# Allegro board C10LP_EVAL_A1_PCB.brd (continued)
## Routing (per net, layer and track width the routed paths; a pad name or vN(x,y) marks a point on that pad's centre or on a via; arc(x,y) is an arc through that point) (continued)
C10_M10_IO0: length 44.6
  TOP w0.135: U3.K8 v2(46.15,67.88) ; v2(39.84,33.68) U1.E8
  ART03 w0.102: v2(46.15,67.88) 45.75,68.27 45.75,68.81 45.5,69.06 43.68,69.06 42.52,67.89 42.52,65.13 42.9,64.74 42.9,63.5 43.56,62.84 43.56,60.68 45.8,58.45 45.8,50.27 39.62,44.09 39.62,36.61 40.26,35.97 40.26,34.1 40.13,33.97 v2(39.84,33.68)
C10_M10_IO1: length 50.4
  TOP w0.135: v2(39.04,33.68) U1.E7 ; U3.J8 v2(46.15,67.07)
  ART03 w0.102: v2(39.04,33.68) 38.63,34.09 38.63,35.69 38.13,36.2 38.13,45.52 39.22,46.61 40.03,46.61 44.55,51.13 44.55,56.36 43.64,57.28 43.64,58.52 42.77,59.39 42.09,59.39 41.76,59.72 41.76,61.49 40.49,62.76 40.49,64.41 40.74,64.67 40.74,68.33 41.63,69.22 42.95,69.22 43.31,69.57 46.15,69.57 46.69,69.04 46.69,67.62 v2(46.15,67.07)
C10_M10_IO2: length 41.8
  TOP w0.135: U3.L10 v2(44.55,67.87) ; v2(39.84,32.88) U1.F8
  ART03 w0.102: v2(44.55,67.87) 44.3,68.12 43.66,68.12 43.33,67.79 43.33,63.63 43.97,62.99 43.97,60.88 46.2,58.65 46.2,49.99 40.69,44.48 40.69,38.51 39.85,37.67 39.85,36.7 40.49,36.07 40.49,33.53 40.23,33.27 v2(39.84,32.88)
C10_M10_IO3: length 58.3
  TOP w0.135: U3.L5 v2(49.35,68.67) ; v2(35.84,35.28) U1.C3
  ART03 w0.102: v2(35.84,35.28) 35.38,35.28 35.37,35.29 34.96,35.29 33.07,37.19 33.07,46.48 35.53,48.95 41,48.95 42.8,50.75 42.8,57.66 42.6,57.86 41.45,57.86 40.97,58.34 40.97,61.11 39.67,62.41 39.67,64.82 39.14,65.35 39.14,68.22 41.91,70.99 48.41,70.99 49.35,70.06 v2(49.35,68.67)
C10_MSEL0: length 8.7
  TOP w0.135: v2(44.64,31.28) U1.H13
  BOTTOM w0.135: R23.1 R22.1 49,31.32 47.52,32.79 46.39,32.79 45.84,32.24 45.84,31.92 45.6,31.68 45.04,31.68 v2(44.64,31.28)
C10_MSEL1: length 9.7
  TOP w0.135: v2(43.84,31.28) U1.H12
  BOTTOM w0.135: R20.1 R19.1 50.13,32.16 48.62,32.16 47.65,33.12 46.25,33.12 45.61,32.48 45.6,32.48 44.48,32.48 44.24,32.24 44.24,31.68 v2(43.84,31.28)
C10_MSEL2: length 7
  TOP w0.135: U1.G12 v2(43.84,32.08)
  BOTTOM w0.135: R17.1 R18.1 48.12,33.53 45.97,33.53 45.72,33.27 45.61,33.27 45.6,33.28 44.48,33.28 44.24,33.04 44.24,32.72 43.84,32.32 v2(43.84,32.08)
C10_NCE: length 7.5
  TOP w0.135: v2(35.84,29.68) U1.J3
  ART03 w0.102: v2(35.84,29.68) 35.55,29.97 30.66,29.97 v1(30.05,29.36)
  BOTTOM w0.135: R8.2 v1(30.05,29.36)
C10_NCONFIG: length 63
  TOP w0.135: v1(66.84,45.83) 66.84,46.67 67.02,46.85 C205.1 68.38,46.85 68.4,46.84 S1.2 ; v2(37.44,31.28) U1.H5
  ART03 w0.102: v1(48.29,40.26) 48.29,39.62 53.92,33.99 62.36,33.99 67.34,38.96 67.34,45.34 v1(66.84,45.83) ; v2(37.44,31.28) 37.03,31.69 37.03,40.87 v1(35.66,42.24)
  BOTTOM w0.135: v2(37.44,31.28) 37.04,31.68 36.48,31.68 36.1,31.68 36.02,31.6 R2.2 ; v1(48.29,40.26) 41.1,40.26 39.12,42.24 v1(35.66,42.24)
C10_NSTATUS: length 92.3
  TOP w0.135: v2(36.64,32.88) U1.F4 ; v2(53.14,70.08) 52.55,69.49 51.77,69.49 U3.M2
  ART03 w0.102: v2(36.64,32.88) 36.25,33.27 33.06,33.27 24.12,42.21 21.18,42.21 20.19,43.21 20.19,44.75 19.68,45.26 19.68,46.48 19.05,47.12 19.05,49.78 20.42,51.16 20.42,55.3 21.03,55.91 28.52,55.91 30.02,54.41 31.7,54.41 32.44,53.67 37.39,53.67 37.8,54.08 37.8,56.01 38.13,56.34 39.37,56.34 40.56,57.53 40.56,60.93 39.19,62.31 39.19,63.17 38.63,63.73 38.63,68.33 41.71,71.4 52.32,71.4 53.14,70.59 v2(53.14,70.08)
  BOTTOM w0.135: v2(36.64,32.88) 36.24,33.28 33.43,33.28 R1.2
C10_RESETN: length 38
  TOP w0.135: U1.J15 46.24,30.48 47.9,30.48 48.26,30.12 50.67,30.12 51.08,29.72 R136.2 51.45,29.35 51.87,28.93 56.46,28.93 v1(58.8,26.59) ; v1(66.84,42.53) C204.1 68.29,42.53 68.4,42.42 S2.2
  BOTTOM w0.135: v1(58.8,26.59) 60.02,27.81 60.02,32.23 65.13,37.34 65.81,37.34 67.36,38.89 67.36,42.01 v1(66.84,42.53)
C10_RG_TXCLK: length 3.6
  TOP w0.135: U1.D3 v2(35.84,34.48)
  BOTTOM w0.135: v2(35.84,34.48) 33.76,34.48 R305.2
C10_RG_TXCTL: length 2.8
  TOP w0.135: v2(38.24,34.48) U1.D6
  BOTTOM w0.135: v2(38.24,34.48) 38.64,34.88 38.64,36 R301.2
C10_RG_TXD0: length 3.7
  TOP w0.135: v2(38.24,33.68) U1.E6
  BOTTOM w0.135: v2(38.24,33.68) 37.84,34.08 37.84,35.73 R306.2
C10_RG_TXD1: length 1.5
  TOP w0.135: v2(35.84,36.88) U1.A3
  BOTTOM w0.135: R303.2 36.14,37.18 v2(35.84,36.88)
C10_RG_TXD2: length 2.5
  TOP w0.135: v2(35.84,36.08) U1.B3
  BOTTOM w0.135: v2(35.84,36.08) 35.44,36.48 35.44,37.42 R304.2
C10_RG_TXD3: length 1.9
  TOP w0.135: v2(35.04,36.88) U1.A2
  BOTTOM w0.135: v2(35.04,36.88) 34.91,36.88 R302.2
C10_USB_CLK: length 3.1
  TOP w0.135: v2(41.43,37.85) 41.48,37.8 41.48,36.12 U1.B9
  BOTTOM w0.135: R248.2 41.41,37.86 v2(41.43,37.85)
C10_VCCA: length 6.1
  TOP w0.254: R67.2 v1(52.44,40.32)
  BOTTOM w0.305: L17.1 51.03,36.37 R64.1 51.54,40.32 v1(52.44,40.32)
C10_VCCA_FLT: length 17.1
  TOP w0.305: U1.L12 v2(43.84,28.08) ; U1.F5 v2(37.44,32.88) ; U1.L5 v2(37.44,28.08) ; U1.F12 v2(43.84,32.88)
  ART03 w0.305: v2(43.84,28.08) 43.83,28.08 43.38,27.64
  ART03 w0.406: v2(43.04,33.68) 43.05,33.68 43.84,32.89 v2(43.84,32.88) 43.45,32.49 43.41,32.49
  BOTTOM w0.135: v2(37.44,28.08) 37.04,28.48 37.04,29.84 37.03,29.85 37.03,29.96
  BOTTOM w0.254: 37.03,29.96 R7.1
  BOTTOM w0.305: L17.2 R17.2 50.13,34.25 50.77,34.9 51.28,34.9 52.02,34.16 52.02,32.69 51.71,32.38 R19.2 R22.2 ; R4.1 R7.1
C10_VCCD_PLL: length 9.1
  TOP w0.305: U1.N4 37.03,26.88 v2(36.64,26.49) ; v2(44.64,34.48) U1.D13 ; v2(44.64,26.48) U1.N13 ; U1.D4 37.04,34.08 v2(36.64,34.48)
  ART03 w0.305: v1(48.59,22.2) 47.75,23.04 47.75,24.28 47.14,24.89 47.14,25.6 46.27,26.48 v2(44.64,26.48)
  vias: v1(53.39,27.84) v1(53.42,27.15) v1(54.13,27.86) v1(54.18,27.15)
C10_VCCINT: length 48.8
  TOP w0.254: R65.2 v1(59.96,36.13)
  TOP w0.305: v2(41.44,32.08) U1.G9 ; U1.K10 v2(42.24,28.88) ; v2(41.44,28.88) U1.K9 ; C143.2 49.9,26.59 v1(48.18,26.59) ; v2(42.24,32.08) U1.G10 ; v2(43.04,32.88) U1.F11 ; v2(42.24,27.28) U1.M11 ; v2(39.04,28.88) U1.K7 ; v2(38.24,31.28) U1.H6 ; v2(43.04,31.28) U1.H11 ; v2(38.24,32.08) U1.G6 ; v2(39.04,32.88) U1.F7 ; v2(38.24,28.08) U1.L6 ; v2(43.84,29.68) U1.J12 ; v2(43.04,28.88) U1.K11 ; U1.M9 41.01,27.68 v2(40.64,27.3) ; v2(38.24,29.68) U1.J6 ; v2(39.84,32.08) U1.G8 ; v2(39.04,32.08) U1.G7
  BOTTOM w0.254: R63.1 55.26,22.4 53.17,22.4 52.75,22.4 52.04,23.11 52.04,29.69 57.12,34.77 57.12,35.98 57.12,36.42 58.14,37.44 59.08,37.44 59.66,36.86 59.66,36.43 v1(59.96,36.13)
  BOTTOM w0.305: C130.1 48.28,26.69 v1(48.18,26.59) ; C194.1 47.7,21.92 v1(48.56,21.06) ; v1(51.51,27.2) 51.49,27.18 51.46,27.18 50.94,26.66 C142.1 ; C193.1 50.01,23.72 50.42,24.13 v1(50.42,24.61)
  BOTTOM w0.406: v2(43.84,29.68) 44.23,30.07 C136.1 ; v2(38.24,31.28) 38.44,31.08 C139.2 ; C134.1 41.02,28.46 v2(41.44,28.88) ; v2(43.04,31.28) 42.84,31.08 C138.2 ; v2(41.44,32.08) 41.03,31.67 C141.1 ; C129.1 v2(40.64,27.3) ; C124.1 39.84,32.08 v2(39.84,32.08)
  vias: v3(59.77,21.56) v3(59.77,20.83) v3(59.77,20.09) v3(60.5,21.62) v3(60.5,20.85) v3(60.5,20.09) v3(60.48,19.3) v3(61.24,21.62) v3(61.24,20.85) v3(61.24,20.12) v3(61.21,19.33)
C10_VCCIO_1.8V: length 6.4
  TOP w0.305: U1.P10 41.87,26.08 42.16,25.79 42.16,25.76 v2(42.21,25.7) ; v2(44.64,25.68) U1.P13 ; v2(47.04,24.08) U1.T16
  BOTTOM w0.305: 47.07,24.11 v2(47.04,24.08)
  BOTTOM w0.406: 47.07,24.11 47.07,25.92 R12.1 ; C122.2 44.7,25.62 v2(44.64,25.68) ; C197.1 42.24,25.68 v2(42.21,25.7)
C10_VCCIO_3.3V: length 33.9
  TOP w0.254: R78.2 v1(52.49,47.08)
  TOP w0.305: v2(36.64,25.68) U1.P4 ; v2(36.64,35.28) 37.04,34.88 U1.C4 ; v2(45.44,33.68) U1.E14 ; v2(35.84,27.28) U1.M3 ; v2(35.84,32.08) U1.G3 ; U1.T1 34.59,24.48 v2(34.24,24.83) ; v2(42.24,35.28) U1.C10 ; v2(39.04,35.28) U1.C7 ; v2(39.04,25.68) U1.P7 ; v2(44.64,35.28) U1.C13 ; v2(45.44,28.88) U1.K14 ; R136.1 R207.1 49.47,28.46 v1(49.35,28.58) ; v2(47.04,36.88) U1.A16 ; v2(34.24,36.88) U1.A1 ; v2(35.84,28.88) U1.K3 ; v2(35.84,33.68) U1.E3 ; v2(44.64,27.28) U1.M14 ; v2(45.44,32.08) U1.G14
  TOP w0.381: R276.1 29.98,25.49 v1(29.96,25.51) R277.1
  ART03 w0.305: 45.19,31.88 45.39,32.08 v2(45.44,32.08)
  BOTTOM w0.254: v1(40.13,39.88) R278.1 R279.1
  BOTTOM w0.305: v1(52.49,47.08) 52.32,47.24 48.48,47.24 R77.1 ; R1.1 33.4,31.8 33.62,31.59 34.39,31.59 R2.1 34.4,32 34.71,32.31 35.61,32.31 v2(35.84,32.08)
  BOTTOM w0.381: v2(35.84,28.88) 35.19,28.88 R288.1
  BOTTOM w0.406: C195.1 47.78,45.47 47.8,45.49 R77.1 ; v1(49.35,28.58) 49.35,29.17 49.05,29.48 R246.1 R21.1 R16.1 46.04,29.48 v2(45.44,28.88) ; C120.2 34.19,36.83 v2(34.24,36.88) ; C196.1 39.03,25.67 v2(39.04,25.68)
  vias: v1(47.8,43.54) v1(47.83,42.85) v1(47.83,42.16)
ENET_CLK_125M: length 60.9
  TOP w0.135: U1.T8 40.16,24.4 40.16,22.4 39.14,21.39 39.14,20.37 37.85,19.08 37.85,16 39.88,13.97 39.88,12.75 42.09,10.54 57.33,10.54 59.77,12.98 62.05,12.98 62.33,12.7 65.35,12.7 v1(66.45,11.61)
  BOTTOM w0.135: R152.2 71.78,23.49 71.2,24.08 68.1,24.08 67.74,23.72 67.74,21.51 67.11,20.88 67.11,12.27 v1(66.45,11.61)
ENET_INT: length 24.8
  TOP w0.135: U1.B5 37.47,36.05 37.47,37.31 33.93,40.84 25.98,40.84 22.99,43.84 22.99,44.54 R97.1
  TOP w0.142: R97.1 22.4,45.42 23.37,46.38 23.37,47.78 23.91,48.32 U14.47
ENET_LED0: length 24.4
  TOP w0.135: v1(17.78,58.52) 17.12,57.86 D10.1 ; U14.24 31.66,53.32 32.07,53.73 R109.2 C55.2 v1(32.84,57.51)
  ART03 w0.102: v1(32.84,57.51) 32.23,58.12 20.95,58.12 20.55,58.52 v1(17.78,58.52)
ENET_LED1: length 26.1
  TOP w0.135: v1(16.89,58.6) 16.1,59.39 D11.1 ; U14.23 31.92,52.82 32.92,53.82 v1(32.92,56.11)
  ART03 w0.102: v1(32.92,56.11) 32.23,56.79 26.04,56.79 25.43,57.4 18.08,57.4 v1(16.89,58.6)
  BOTTOM w0.135: C56.2 R112.2 16.87,58.62 v1(16.89,58.6)
ENET_LED2: length 28.3
  TOP w0.135: v1(17.86,59.36) 16.33,60.88 D12.1 ; U14.22 32.05,52.32 33.64,53.91 C65.2 R114.2 v1(32.84,59.03)
  ART03 w0.102: v1(17.86,59.36) 18.26,58.95 20.88,58.95 21.26,58.57 32.38,58.57 v1(32.84,59.03)
ENET_MDC: length 32
  TOP w0.135: R297.1 20,45.15 19.56,44.7 19.56,43.43 20.5,42.49 23.04,42.49 25.6,39.93 33.48,39.93 36.65,36.75 36.65,36.07 U1.B4
  TOP w0.142: R297.1 20.68,45.63 21.04,45.63 22.38,46.96 22.38,48.57 22.21,48.74 22.21,50.15 23.38,51.32 U14.41
ENET_MDIO: length 28.2
  TOP w0.135: U1.A4 37.04,37.1 33.76,40.39 25.78,40.39 23.19,42.98 22.17,42.98 21.84,43.31 21.84,44.49 R98.1 21.21,45.14 21.34,45.26
  TOP w0.142: U14.42 23.41,50.82 22.66,50.06 22.66,48.92 22.86,48.72 22.86,46.79 21.34,45.26
ENET_REGO: length 4
  TOP w0.254: 21.84,53.17 22.68,52.32 U14.39
  TOP w0.305: 20.73,53.17 21.84,53.17
ENET_RG_RXCLK: length 17.7
  TOP w0.135: U1.B8 39.84,36.08 39.84,39.31 37.87,41.27 37.87,42.65 36.28,44.23 R102.1
ENET_RG_RXCTL: length 18.2
  TOP w0.135: R103.1 26.4,41.3 34.11,41.3 37.84,37.57 U1.A5
ENET_RG_RXD0: length 17.1
  TOP w0.135: U1.A7 39.44,38.86 37.03,41.27 37.03,42.65 36.4,43.28 28.74,43.28 R104.1
ENET_RG_RXD1: length 18.9
  TOP w0.135: R105.1 26.64,43.46 27.38,42.72 35.97,42.72 36.37,42.32 36.37,41.15 39.04,38.48 39.04,36.08 U1.B7
ENET_RG_RXD2: length 17.5
  TOP w0.135: R106.1 25.63,43.74 27.15,42.21 34.54,42.21 38.64,38.12 U1.A6
ENET_RG_RXD3: length 18.7
  TOP w0.135: R107.1 26.96,41.76 34.32,41.76 38.25,37.82 38.25,36.07 U1.B6
ENET_RG_TXCLK: length 13.6
  TOP w0.142: v1(30.07,44.83) 29.72,45.19 29.72,45.75 29.11,46.36 U14.9
  BOTTOM w0.135: v1(30.07,44.83) 30.07,39.05 31.03,38.1 32.56,38.1 33.1,37.57 R305.1
ENET_RG_TXCTL: length 14.9
  TOP w0.135: U14.15 32.08,48.82 33.07,47.83 33.07,45.39 v1(33.63,44.83)
  BOTTOM w0.135: R301.1 37.24,38.29 37.24,39.65 33.63,43.26 v1(33.63,44.83)
ENET_RG_TXD0: length 14.7
  TOP w0.135: v1(31.8,45.69) 32.26,45.69 32.61,46.05 32.61,47.6 31.89,48.32 U14.14
  BOTTOM w0.135: R306.1 36.73,37.73 36.73,39.4 32.28,43.84 32.28,45.21 v1(31.8,45.69)
ENET_RG_TXD1: length 14.7
  TOP w0.135: v1(31.78,44.86) 31.32,45.31 31.32,46.1 30.61,46.81 U14.12
  BOTTOM w0.135: v1(31.78,44.86) 31.78,42.32 31.91,42.19 32.48,42.19 32.61,42.05 32.61,41.79 32.48,41.65 31.91,41.65 31.78,41.52 31.78,41.22 31.93,41.07 33.28,41.07 33.41,40.94 33.41,40.5 33.55,40.36 33.81,40.36 33.95,40.5 33.95,40.99 34.08,41.12 34.37,41.12 36.14,39.34 R303.1
ENET_RG_TXD2: length 13.6
  TOP w0.135: U14.11 30.11,46.68 30.84,45.95 v1(30.84,45.69)
  BOTTOM w0.135: v1(30.84,45.69) 31.29,45.24 31.29,39.99 31.43,39.85 31.68,39.85 31.82,39.99 31.82,40.4 31.95,40.54 32.22,40.54 32.35,40.4 32.35,39.99 32.49,39.85 34.85,39.85 35.1,39.6 R304.1
ENET_RG_TXD3: length 14.1
  TOP w0.135: U14.10 29.61,46.54 30.25,45.9 30.25,45.42 v1(30.81,44.86)
  BOTTOM w0.135: R302.1 33.49,38.65 33.36,38.78 33.36,39.16 33.17,39.34 32.96,39.34 32.82,39.21 32.82,38.78 32.69,38.65 32.27,38.65 32.14,38.78 32.14,39.21 31.98,39.37 31.73,39.37 31.6,39.24 31.6,38.78 31.46,38.65 31.18,38.65 30.81,39.01 v1(30.81,44.86)
ENET_RSTN: length 18.4
  TOP w0.135: v1(33.6,45.69) 33.62,45.71 R96.1 C54.2 32.84,48.69 32.21,49.32 U14.16 ; v2(38.24,35.28) U1.C6
  ART03 w0.102: v1(33.6,45.69) 37.47,41.83 37.47,36.05 v2(38.24,35.28)
ENET_TCK: length 3.1
  TOP w0.135: v1(32.21,50.85) 31.39,50.85 U14.19
  BOTTOM w0.135: R99.1 31.24,51.82 v1(32.21,50.85)
ENET_TDI: length 2
  TOP w0.135: TP6.1 32.61,50.32 U14.18
ENET_TDO: length 1.3
  TOP w0.135: TP5.1 31.36,51.82 U14.21
ENET_TMS: length 3.5
  TOP w0.135: U14.20 32.01,51.32 32.05,51.36 32.59,51.36 TP7.1
ENET_VDD_1V: length 5.5
  TOP w0.254: v1(32.08,46.63) 32.08,47.37 31.63,47.82 U14.13 ; U14.8 28.61,46.68 28.68,46.61 28.68,46.1 v1(28.88,45.9) ; v1(22.78,51.61) 22.99,51.82 U14.40 ; U14.17 v1(32.27,49.82)
  vias: v1(21.01,49.83) v1(20.95,48.82) v1(21.64,49.45)
ENET_VDD_3.3V: length 24.8
  TOP w0.203: U14.45 23.9,49.32 v1(23.47,48.89)
  TOP w0.254: U14.38 23.81,52.82 23.32,53.31 23.32,53.45 C64.2 ; U14.25 30.61,54.84 v1(30.76,54.99) ; U14.2 v1(25.61,46.23) ; v1(25.45,54.94) 25.61,54.79 U14.35 ; v1(28.09,46.2) 28.11,46.22 U14.7 ; v1(28.12,54.97) 28.11,54.95 U14.30
  TOP w0.305: R97.2 v1(22.4,43.56)
  TOP w0.381: v1(21.54,54.56) 21.79,54.31 v1(22.33,54.31) 22.9,53.73 C64.2 ; R98.2 21.21,43.94 v1(20.83,43.56) 20.19,44.2 R297.2
  TOP w0.406: R96.2 v1(34.51,47.02)
  BOTTOM w0.381: v1(23.47,48.89) 23.6,49.02 C60.2 ; v1(28.09,46.2) 28.11,46.22 28.11,46.76 C62.2 ; R99.2 31.25,53.54 31.8,53.54 31.85,53.49 31.85,52.43 33.58,50.7 33.58,47.94 v1(34.51,47.02) ; v1(25.61,46.23) 26.29,46.91 C61.2
  BOTTOM w0.406: C57.2 25.91,54.98 25.87,54.94 v1(25.45,54.94) ; C58.2 v1(28.12,54.97)
ENET_XTAL1: length 5.3
  TOP w0.135: U14.36 25.11,54.54 C44.1 23.37,56.27
  TOP w0.142: 23.37,56.27 23.37,57.95 23.5,58.08 Y2.3
ENET_XTAL2: length 4.3
  TOP w0.135: C53.1 24.36,54.22 U14.37
  TOP w0.142: Y2.1 22.62,55.96 C53.1
EXT_JTAG_TCK: length 46.9
  TOP w0.135: v1(53.87,83.41) 54.58,82.7 R57.2 54.6,81.41 R58.1 53.21,81.28 52.91,80.98 51.31,80.98 50.44,81.84 J2.1 ; v2(41.78,65.99) 42.07,66.27 42.95,66.27 U3.J12
  ART03 w0.102: v1(38,79.63) 37.24,80.39 37.24,81.89 37.62,82.27 52.73,82.27 v1(53.87,83.41)
  BOTTOM w0.135: v2(41.78,65.99) 41.53,65.74 39.4,65.74 38,67.13 v1(38,79.63)
EXT_JTAG_TDI: length 33.8
  TOP w0.135: J2.9 v1(40.28,80.77) ; U3.J9 v2(45.35,67.07)
  ART03 w0.102: v1(39.98,67.54) 39.98,68.05 41.5,69.57 42.9,69.57 43.41,70.08 46.28,70.08 46.91,69.44 46.91,66.95 46.63,66.67 45.75,66.67 v2(45.35,67.07)
  BOTTOM w0.135: v1(39.98,67.54) 38.61,68.91 38.61,79.98 38.25,80.34 R61.2 37.55,80.77 v1(40.28,80.77)
EXT_JTAG_TDO: length 25.4
  TOP w0.135: J2.3 v1(47.9,80.72) ; v1(39.52,70.76) 40.23,70.05 40.23,68.71 41.87,67.07 42.95,67.07 U3.K12
  ART03 w0.102: v1(47.9,80.72) 47.14,79.96 41.68,79.96 40.01,78.28 40.01,75.06 39.42,74.47 39.42,70.87 v1(39.52,70.76)
EXT_JTAG_TMS: length 36.2
  TOP w0.135: R60.2 53.47,79.6 v1(53.44,79.58) 52.88,80.14 46.08,80.14 45.36,80.85 J2.5 ; v1(40.51,73.28) 40.51,71.25 41,70.76 41,68.91 41.63,68.27 U3.L13
  ART03 w0.102: v1(40.51,73.28) 40.51,77.29 42.72,79.5 53.37,79.5 v1(53.44,79.58)
EXT_VREF: length 11.2
  TOP w0.147: U3.D3 v2(50.16,62.29)
  BOTTOM w0.305: v2(50.16,62.29) 50.16,62.15 51.24,61.07 C213.2
  BOTTOM w0.406: R228.1 48.06,57.4 48.79,56.67 R295.2 51.32,58.48 C212.1 51.24,58.56 C213.2
EXT_VREF_AR: length 60.7
  TOP w0.381: v1(28.4,13.13) 27.01,13.13 R308.2
  ART03 w0.305: v1(42.32,57.33) 40.36,55.37 40.36,51.74 39.29,50.67 34.44,50.67 29.46,45.69 29.46,38.35 v1(30.07,37.74)
  BOTTOM w0.305: v1(42.32,57.33) 44.07,57.33 44.3,57.1 45.21,57.1 45.52,57.4 R228.2 ; v1(30.07,37.74) 30.07,35.92 31.9,34.09 31.9,27.1 30.78,25.98 30.78,20.55 31.24,20.09 31.24,17.45 28.93,15.14 28.93,13.67 v1(28.4,13.13)
FX2_D_N: length 17.4
  TOP w0.132: U6.9 67.4,70.69 67.49,70.61 69.91,70.61 70.25,70.94 71.15,70.94 71.48,70.62 71.68,70.62 U5.2 72.03,70.61 76.1,70.61 77.24,69.47 77.24,66.54 J17.2
FX2_D_P: length 17.3
  TOP w0.132: U6.8 67.4,70.19 67.49,70.28 69.94,70.28 70.29,69.93 71.14,69.93 71.42,70.21 71.73,70.21 U5.1 72.03,70.28 75.96,70.28 76.91,69.33 76.91,66.67 75.31,65.07 J17.3
FX2_FLAGA: length 17.9
  TOP w0.135: U6.29 58.78,73.19 58.5,73.48 58.5,73.58 v1(58.09,73.99) ; U3.M9 46.15,69.48 46.15,71.73 46.63,72.21 v1(46.63,73.63)
  ART03 w0.102: v1(46.63,73.63) 57.73,73.63 v1(58.09,73.99)
FX2_FLAGB: length 15.5
  TOP w0.135: v1(58.12,73) 58.42,72.69 U6.30 ; v1(47.37,73.13) 46.99,72.75 46.99,71.5 46.55,71.06 U3.N8
  ART03 w0.102: v1(58.12,73) 57.99,73.13 v1(47.37,73.13)
FX2_FLAGC: length 17
  TOP w0.135: U6.31 58.06,72.19 55.8,74.45 49.68,74.45 47.37,72.14 47.37,71.04 46.94,70.61 46.94,69.47 U3.M8
FX2_PA0: length 15.6
  TOP w0.135: U6.33 58.32,71.19 58.32,71.19 58.07,71.19 57.74,71.52 57.74,71.85 55.68,73.91 49.78,73.91 47.75,71.88 47.75,70.89 47.35,70.48 U3.N7
FX2_PA1: length 15.8
  TOP w0.135: U6.34 58.17,70.69 58.1,70.76 57.87,70.76 57.3,71.32 57.3,71.4 55.24,73.46 49.96,73.46 48.13,71.63 48.13,70.62 47.75,70.23 47.75,69.47 U3.M7
FX2_PA2: length 14.1
  TOP w0.135: U6.35 57.79,70.19 54.99,73 50.04,73 48.5,71.46 48.5,70.23 U3.N6
FX2_PA3: length 13.2
  TOP w0.135: U3.N5 48.95,71.29 50.2,72.54 54.74,72.54 57.59,69.69 U6.36
FX2_PA4: length 14
  TOP w0.135: U6.37 57.45,69.19 56.85,69.8 55.75,69.8 55.4,70.15 55.4,70.92 54.23,72.09 50.27,72.09 49.35,71.16 49.35,69.47 U3.M5
FX2_PA5: length 12.2
  TOP w0.135: U6.38 57.24,68.69 56.59,69.34 55.55,69.34 54.91,69.98 54.91,70.51 53.8,71.63 50.39,71.63 49.75,70.98 U3.N4
FX2_PA6: length 12.9
  TOP w0.135: U6.39 55.25,68.19 54.71,68.73 54.71,69.49 54.28,69.93 54.28,70.41 53.52,71.17 50.55,71.17 50.15,70.77 50.15,69.47 U3.M4
FX2_PA7: length 11.7
  TOP w0.135: U3.M3 50.95,69.48 50.95,70.36 51.31,70.71 53.24,70.71 53.71,70.24 53.71,69.74 54.25,69.19 54.25,68.45 55.01,67.69 U6.40
FX2_PB0: length 35.1
  TOP w0.135: U6.18 64.71,75.77 61.94,78.54 53.34,78.54 v1(53.31,78.51) ; v1(41.81,71.96) 41.81,69.81 U3.M13
  ART03 w0.102: v1(41.81,71.96) 41.81,73.96 41.22,74.55 41.22,76 43.74,78.51 v1(53.31,78.51)
FX2_PB1: length 33.4
  TOP w0.135: U3.M12 42.98,69.44 42.98,70.64 42.32,71.3 v1(42.32,72.9) ; v1(54.13,78.05) 61.72,78.05 64.21,75.56 U6.19
  ART03 w0.102: v1(54.13,78.05) 44.07,78.05 42.32,76.3 42.32,75.59 41.88,75.16 41.88,74.5 42.32,74.07 v1(42.32,72.9)
FX2_PB2: length 30.4
  TOP w0.135: U6.20 63.71,75.41 61.57,77.55 v1(53.29,77.55) ; U3.N12 43.36,69.89 43.36,70.89 42.85,71.4 v1(42.85,71.98)
  ART03 w0.102: v1(53.29,77.55) 44.27,77.55 42.85,76.12 v1(42.85,71.98)
FX2_PB3: length 29.7
  TOP w0.135: v1(54.13,77.06) 61.35,77.06 63.21,75.2 U6.21 ; v1(43.33,72.9) 43.33,71.48 43.74,71.07 43.74,69.48 U3.M11
  ART03 w0.102: v1(43.33,72.9) 43.33,75.97 44.42,77.06 v1(54.13,77.06)
FX2_PB4: length 29
  TOP w0.135: U6.22 62.71,74.99 61.12,76.58 v1(53.26,76.58) ; U3.L11 44.53,68.66 44.53,70.84 43.89,71.48 v1(43.89,71.96)
  ART03 w0.102: v1(43.89,71.96) 43.89,75.92 44.55,76.58 v1(53.26,76.58)
FX2_PB5: length 25.4
  TOP w0.135: U3.N10 44.95,70.88 44.42,71.4 v1(44.42,72.92) ; v1(54.13,76.07) 60.9,76.07 62.21,74.76 U6.23
  ART03 w0.102: v1(44.42,72.92) 44.42,75.59 44.91,76.07 v1(54.13,76.07)
FX2_PB6: length 24.7
  TOP w0.135: v1(44.91,71.93) 44.91,71.35 45.36,70.89 45.36,69.49 U3.M10 ; v1(53.21,75.59) 54.66,75.59 54.69,75.62 60.65,75.62 61.71,74.55 U6.24
  ART03 w0.102: v1(53.21,75.59) 52.5,74.88 49.83,74.88 49.23,75.49 45.92,75.49 44.91,74.47 v1(44.91,71.93)
FX2_PB7: length 21.1
  TOP w0.135: U3.N9 45.75,71.04 45.42,71.37 v1(45.42,72.92) ; v1(54.1,75.11) 54.91,75.11 54.97,75.16 60.48,75.16 61.21,74.42 U6.25
  ART03 w0.102: v1(54.1,75.11) 53.19,74.19 46.18,74.19 45.42,73.43 v1(45.42,72.92)
FX2_PD0: length 2.7
  TOP w0.135: U6.45 v1(60.71,64.24)
  BOTTOM w0.135: R35.1 60.71,63.32 v1(60.71,64.24)
FX2_PD1: length 5.3
  TOP w0.135: U6.46 v1(61.21,65.1)
  BOTTOM w0.135: R34.1 62.42,61.71 61.21,62.92 v1(61.21,65.1)
FX2_PD2: length 3.9
  TOP w0.135: U6.47 v1(61.71,64.24)
  BOTTOM w0.135: v1(61.71,64.24) 61.71,63.24 R36.1
FX2_PD3: length 2.7
  TOP w0.135: U6.48 v1(62.21,65.1)
  BOTTOM w0.135: v1(62.21,65.1) 62.21,63.78 R37.1
FX2_PD4: length 19.1
  TOP w0.135: U3.J7 v2(47.75,67.07) ; U6.49 v1(62.71,64.24)
  ART03 w0.102: v2(47.75,67.07) 48.15,66.67 51.16,66.67 51.54,67.06 56.87,67.06 58.19,65.74 61.34,65.74 61.72,65.35 61.72,64.9 62,64.62 62.33,64.62 v1(62.71,64.24)
FX2_PD5: length 20.7
  TOP w0.135: U6.50 v1(63.21,65.1) ; U3.K7 v2(47.75,67.88)
  ART03 w0.102: v2(47.75,67.88) 48.16,67.46 49.5,67.46 49.73,67.69 49.73,68.07 49.94,68.28 50.42,68.28 50.83,67.87 56.34,67.87 56.77,68.3 62.18,68.3 62.43,68.05 62.43,67.28 63.21,66.51 v1(63.21,65.1)
FX2_PD6: length 19
  TOP w0.135: U6.51 63.71,64.45 v1(63.53,64.26) ; U3.J5 v2(49.35,67.07)
  ART03 w0.102: v2(49.35,67.07) 49.6,67.07 49.99,67.46 56.52,67.46 56.74,67.69 60.02,67.69 60.6,67.11 61.77,67.11 62.71,66.17 62.71,64.9 63.02,64.59 63.2,64.59 v1(63.53,64.26)
FX2_PD7: length 18.9
  TOP w0.135: U3.L4 v2(50.15,68.67) ; U6.52 v1(64.21,65.1)
  ART03 w0.102: v2(50.15,68.67) 50.4,68.67 50.8,68.28 56.16,68.28 56.64,68.76 62.94,68.76 63.5,68.2 63.5,67.36 64.21,66.65 v1(64.21,65.1)
FX2_RESETN: length 8.9
  TOP w0.135: v2(54.58,65.33) 54.03,65.33 52.68,66.67 U3.J1 ; U6.42 58.54,66.69 v1(58.28,66.43)
  BOTTOM w0.135: v1(58.28,66.43) 58.06,66.65 U4.2 57.52,66.64 R27.1 57.37,65.33 v2(54.58,65.33)
FX2_SCL: length 26.6
  TOP w0.135: R29.1 66.83,74.8 v1(66.8,74.83) 66.21,74.24 U6.15 ; U3.J6 v2(48.55,67.07)
  BOTTOM w0.135: v1(66.8,74.83) 66.67,74.83 65.84,75.67 58.67,75.67 54.31,71.3 50.27,71.3 49.74,70.77 49.74,68.51 49.51,68.28 49.48,68.28 49.48,68.28 49.15,68.28 48.95,68.07 48.95,67.48 v2(48.55,67.07)
FX2_SDA: length 23.2
  TOP w0.135: U6.16 65.71,74.5 v1(66.83,75.62) 67.08,75.87 R30.1
  BOTTOM w0.135: R26.2 50.11,71.77 54.11,71.77 58.47,76.12 66.32,76.12 v1(66.83,75.62)
FX2_SLRDN: length 25.4
  TOP w0.135: U3.K5 v2(49.35,67.88) ; U6.1 67.11,66.69 67.41,66.4 67.41,66.04 v1(66.65,65.28)
  ART03 w0.102: v2(49.35,67.88) 49.35,68.12 49.73,68.5 49.73,69.22 50.22,69.7 59.69,69.7 60.2,70.21 64.92,70.21 65.63,69.49 65.63,66.29 v1(66.65,65.28)
FX2_SLWRN: length 25.5
  TOP w0.135: v1(66.29,64.52) 67.13,64.52 67.87,65.25 67.87,66.62 67.3,67.19 U6.2 ; U3.L3 v2(50.95,68.68)
  ART03 w0.102: v2(50.95,68.68) 51.56,69.29 60.07,69.29 60.55,69.77 64.41,69.77 64.64,69.55 64.64,65.41 65.53,64.52 v1(66.29,64.52)
FX2_WAKEUP: length 4.4
  TOP w0.135: U6.44 v1(60.21,65.1)
  BOTTOM w0.135: v1(60.21,65.1) 60.71,65.59 C14.2 R32.2 61.99,65.99 R31.2
GPIO0: length 81.9
  TOP w0.135: U1.L13 v2(44.64,28.08)
  ART03 w0.102: v2(44.64,28.08) 45.03,27.69 46.43,27.69 46.84,27.28 47.7,27.28 47.88,27.1 48.34,27.1 49.48,25.96 50.35,25.96 52.1,24.22 52.1,23.44 52.93,22.61 54.51,22.61 57.28,19.84 57.28,17.4 56.39,16.51 56.39,11.2 54.51,9.32 43.54,9.32 42.16,10.69 39.37,10.69 38.54,9.86 28.82,9.86 25.35,13.34 25.35,14.35 24.54,15.16 22.07,15.16 20.5,13.59 9.48,13.59 J10.1
GPIO1: length 84.2
  TOP w0.137: v2(47.5,28.48) U1.L16
  ART03 w0.102: v2(47.5,28.48) 47.91,28.07 48.54,28.07 49.83,26.77 50.7,26.77 51.74,25.73 53.77,25.73 54.25,25.25 54.25,24.23 58.12,20.37 58.12,17.04 57.23,16.15 57.23,10.74 54.99,8.51 43.1,8.51 42.09,9.53 39.47,9.53 38.91,8.97 27.98,8.97 24.5,12.45 19.86,12.45 18.59,11.18 9.32,11.18 7.21,9.07 5.08,9.07 4.3,9.85 J10.2
GPIO2: length 85.3
  TOP w0.137: U1.L15 46.24,28.08 47.84,28.08 v1(48.31,27.61)
  ART03 w0.102: J10.3 5.49,12.13 5.49,10.11 5.97,9.63 7.14,9.63 9.25,11.73 18.34,11.73 19.56,12.95 24.87,12.95 28.4,9.42 38.71,9.42 39.57,10.29 41.99,10.29 43.36,8.92 54.76,8.92 56.79,10.95 56.79,16.33 57.68,17.22 57.68,20.07 54.64,23.11 53.06,23.11 52.58,23.6 52.58,24.31 50.52,26.37 49.66,26.37 48.6,27.42 48.5,27.42 v1(48.31,27.61)
GPIO3: length 94.7
  TOP w0.135: 48.82,28.58 48.82,28.75 48.29,29.28
  TOP w0.137: 48.82,28.58 48.82,27.91 49.1,27.64 v1(49.81,27.64) ; 48.29,29.28 U1.K16
  ART03 w0.102: v1(49.81,27.64) 50.27,27.18 50.88,27.18 51.79,26.26 53.92,26.26 54.76,25.43 54.76,24.41 58.56,20.61 58.56,17.72 58.93,17.35 61.16,17.35 61.62,16.89 61.62,14.53 55.17,8.08 43.48,8.08 42.82,7.42 35.33,7.42 34.39,8.36 27.64,8.36 23.95,12.04 20.04,12.04 17.17,9.17 8.28,9.17 7.75,8.64 4.67,8.64 2.82,10.49 2.82,12.01 J10.4
GPIO4: length 74.8
  TOP w0.137: U1.P16 47.24,25.48 v1(48.64,25.48)
  ART03 w0.102: v1(48.64,25.48) 50.22,25.48 51.61,24.08 51.61,23.34 51.79,23.16 51.79,20.37 52.3,19.86 52.3,17.65 55.98,13.97 55.98,11.86 53.85,9.73 43.74,9.73 42.32,11.15 39.22,11.15 38.37,10.3 33.59,10.3 32.79,11.1 28.17,11.1 25.76,13.51 25.76,14.56 24.75,15.57 21.62,15.57 20.68,14.63 18.72,14.63 18.41,14.33 8.53,14.33 J10.5
GPIO5: length 74.1
  TOP w0.135: U1.R16 47.49,24.43 v1(48.67,24.43)
  ART03 w0.102: J10.6 5.59,17.31 5.59,18.87 6.3,19.58 7.98,19.58 10.77,16.79 17.32,16.79 18.57,15.54 20.27,15.54 21.11,16.38 25.08,16.38 26.57,14.9 26.57,14.1 28.63,12.04 33.15,12.04 34.07,11.11 38.01,11.11 38.89,11.99 42.65,11.99 44.07,10.57 51.92,10.57 52.96,11.61 52.96,15.85 50.65,18.16 50.65,19.51 50.04,20.12 50.04,22.78 48.67,24.16 v1(48.67,24.43)
GPIO6: length 71.6
  TOP w0.137: v2(47.5,26.88) U1.N16
  ART03 w0.102: v2(47.5,26.88) 47.65,26.73 47.65,26.31 47.99,25.97 47.99,25.41 48.41,24.99 48.84,24.99 49.23,24.61 49.23,24.18 50.6,22.81 50.6,20.19 51.05,19.74 51.05,18.34 53.37,16.03 53.37,11.3 52.2,10.13 43.92,10.13 42.47,11.58 39.07,11.58 38.19,10.71 33.82,10.71 32.94,11.58 28.45,11.58 26.16,13.87 26.16,14.73 24.91,15.98 21.39,15.98 20.45,15.04 18.39,15.04 17.23,16.19 9.21,16.19 J10.7
GPIO7: length 73.8
  TOP w0.137: v1(48.72,23.42) 49.15,23.85 49.15,25.78 48.87,26.06 47.32,26.06 46.94,26.44 46.28,26.44 46.12,26.6 U1.N15
  ART03 w0.102: v1(48.72,23.42) 49.63,22.5 49.63,19.94 50.19,19.38 50.19,18.03 52.45,15.77 52.45,11.81 51.64,11 44.22,11 42.8,12.42 38.86,12.42 38.3,12.98 33.68,12.98 33.17,12.47 30.35,12.47 28.04,14.78 27.26,14.78 25.25,16.79 20.8,16.79 20.07,16.05 18.75,16.05 17.48,17.32 17.48,18.08 16.76,18.8 9.75,18.8 8.48,20.07 5.8,20.07 J10.8
GPIO8: length 69.1
  TOP w0.135: U1.N14 v2(45.44,27.28)
  ART03 w0.102: J10.9 10.62,21.1 12.45,19.28 17.04,19.28 19.13,17.2 25.42,17.2 27.48,15.14 38.02,15.14 40.34,12.83 42.98,12.83 43.74,12.07 49.48,12.07 50.04,11.51 51.26,11.51 52.02,12.27 52.02,15.42 51.54,15.9 50.09,15.9 49.66,16.33 49.66,19.33 49.23,19.76 49.23,22.23 48.21,23.24 48.21,24.51 47.62,25.1 47.62,25.83 47.52,25.93 47.52,26.01 46.25,27.28 v2(45.44,27.28)
GPIO9: length 66.3
  TOP w0.135: v2(46.23,25.68) 45.84,26.07 U1.P15
  ART03 w0.102: J10.10 5.29,22.1 10.36,22.1 11.18,21.29 17.17,21.29 17.75,20.7 17.75,19.18 19.25,17.68 25.51,17.68 27.47,15.72 38.05,15.72 39.6,14.17 42.22,14.17 43.19,13.2 45.48,13.2 46.2,12.47 48.9,12.47 50.39,13.97 50.39,14.86 49.2,16.05 49.2,19.2 48.79,19.61 48.36,19.61 47.83,20.14 47.83,22.5 46.63,23.7 46.63,25.3 46.25,25.68 v2(46.23,25.68)
GPIO10: length 44
  TOP w0.135: U1.N8 v2(39.84,26.48)
  ART03 w0.102: v2(39.84,26.48) 40.26,26.06 40.26,25.12 38.94,23.8 38.94,21.51 34.42,16.99 27.94,16.99 25.43,19.51 25.13,19.51 24.04,20.6 20.32,20.6 16.48,24.43 14.85,24.43 13.74,25.55 10.01,25.55 9.38,26.18 J10.13
GPIO11: length 46.7
  TOP w0.135: U1.P8 v2(39.84,25.68)
  ART03 w0.102: J10.14 5.29,27.18 9.32,27.18 9.98,26.52 16.54,26.52 17.2,25.86 17.2,24.36 20.45,21.11 24.84,21.11 26.01,19.94 26.01,19.51 28.12,17.4 34.24,17.4 38.51,21.67 38.51,23.93 39.84,25.26 v2(39.84,25.68)
GPIO12: length 55.1
  TOP w0.135: U1.M8 v2(39.84,27.28)
  ART03 w0.102: J10.15 5.8,27.69 4.32,27.69 3.3,26.67 3.3,25.58 3.73,25.15 9.14,25.15 9.53,24.76 13.84,24.76 14.65,23.95 16.38,23.95 20.47,19.86 20.47,18.9 20.88,18.49 25.86,18.49 27.76,16.59 34.67,16.59 39.45,21.36 39.45,23.75 40.51,24.82 40.51,26.42 39.84,27.09 v2(39.84,27.28)
GPIO13: length 55.7
  TOP w0.135: v2(39.84,28.08) U1.L8
  ART03 w0.102: v2(39.84,28.08) 40.23,27.69 40.23,27.05 40.74,26.54 40.74,24.59 39.85,23.7 39.85,21.08 34.95,16.18 27.58,16.18 25.68,18.08 20.68,18.08 20.05,18.71 20.05,19.6 17.93,21.72 14.81,21.72 12.32,24.21 8.94,24.21 8.51,24.64 3.56,24.64 2.79,25.4 2.79,27.22 J10.16
GPIO14: length 51
  TOP w0.137: J10.17 7.92,30.17 7.92,22 13.67,16.26 17.27,16.26 18.44,17.42 19.96,17.42 20.6,16.79 27.23,16.79 28.83,18.39 29.67,18.39 30.56,17.5 35.2,17.5 38.68,20.98 38.68,21.67 39.84,22.83 39.84,24.88 U1.R7
GPIO15: length 53.8
  TOP w0.137: U1.T7 39.44,23.06 38.23,21.84 38.23,21.16 35.03,17.96 30.86,17.96 29.36,19.46 27.79,19.46 25.73,17.4 20.68,17.4 20.14,17.93 18.29,17.93 17.12,16.76 13.89,16.76 8.43,22.23 8.43,31.83 7.87,32.38 5.42,32.38 J10.18
GPIO16: length 46.9
  TOP w0.135: U1.L7 v2(39.04,28.08)
  ART03 w0.102: J10.19 7.85,33.8 14.63,27.03 16.87,27.03 17.68,26.21 17.68,24.46 20.57,21.56 27.15,21.56 29.46,19.25 35.48,19.25 38.1,21.87 38.1,24.16 39.45,25.5 39.45,27.67 v2(39.04,28.08)
GPIO17: length 47.8
  TOP w0.135: U1.M7 v2(39.04,27.28)
  ART03 w0.102: J10.20 4.34,33.8 5.33,34.8 7.75,34.8 13.61,28.93 16.56,28.93 18.19,27.3 19.63,27.3 20.93,26.01 20.93,25.22 24,22.15 27.18,22.15 29.62,19.71 35.28,19.71 37.59,22.02 37.59,24.28 38.63,25.32 38.63,26.87 v2(39.04,27.28)
GPIO18: length 52.6
  TOP w0.135: J10.21 7.47,35.71
  TOP w0.137: U1.R6 39.04,24.88 39.04,23.27 37.77,22 37.77,21.34 34.87,18.44 31.01,18.44 29.54,19.91 27.57,19.91 25.57,17.91 20.93,17.91 20.35,18.49 18.39,18.49 18.03,18.85 12.78,18.85 8.89,22.73 8.89,34.29 7.47,35.71
GPIO19: length 55.2
  TOP w0.135: J10.22 5.55,37.59 7.11,37.59 9.42,35.28 9.42,33.97
  TOP w0.137: 9.42,33.97 9.42,22.91 13.03,19.3 17.35,19.3 17.87,19.82 19.65,19.82 21.06,18.41 25.35,18.41 27.3,20.37 29.72,20.37 31.19,18.9 34.7,18.9 37.31,21.51 37.31,22.15 38.64,23.48 U1.T6
GPIO20: length 36.1
  TOP w0.135: U1.T2 35.28,24.48 34.92,24.13 34.54,24.13 v1(34.04,23.62) ; J10.23 8.84,38.88 v1(10.03,37.68)
  ART03 w0.102: v1(34.04,23.62) 31.01,23.62 27.53,27.1 25.96,27.1 25.4,27.66 23.75,27.66 22.73,28.68 22.73,30.07 19.18,33.63 15.77,33.63 14,35.41 12.31,35.41 v1(10.03,37.68)
GPIO21: length 48.2
  TOP w0.135: U1.M6 v2(38.24,27.28)
  ART03 w0.102: J10.24 4.3,38.88 5.46,37.72 7.37,37.72 7.82,37.26 7.82,36.65 13.03,31.45 17.04,31.45 18.67,29.82 18.67,28.73 19.15,28.24 19.89,28.24 21.79,26.34 21.79,25.55 24.33,23.01 27.48,23.01 29.79,20.7 35.08,20.7 36.68,22.3 36.68,24.33 37.82,25.48 37.82,26.86 v2(38.24,27.28)
GPIO22: length 50.8
  TOP w0.135: J10.25 9.23,41.42 11.66,38.99 11.66,36.07 11.05,35.46 11.05,27.43 14.61,23.88 16.71,23.88 19,21.59 25.58,21.59 26.24,22.25 29.77,22.25 31.7,20.32 34.21,20.32 35.94,22.05 35.94,22.56 37.44,24.05 37.44,24.88 U1.R5
GPIO23: length 53.4
  TOP w0.135: U1.T5 37.84,23.82 36.4,22.38 36.4,21.87 34.39,19.86 31.5,19.86 29.57,21.79 26.42,21.79 25.76,21.13 17.81,21.13 17.14,21.79 15.39,21.79 10.54,26.64 10.54,35.76 11.07,36.3 11.07,38.66 9.55,40.18 5.54,40.18 J10.26
GPIO24: length 48.3
  TOP w0.135: U1.N5 v2(37.44,26.48)
  ART03 w0.102: J10.27 8.23,42.57 8.23,36.91 13.26,31.88 17.37,31.88 19.34,29.91 19.6,29.91 20.1,29.4 20.1,28.61 23.98,24.74 26.34,24.74 29.95,21.13 34.92,21.13 36.27,22.48 36.27,24.77 37.03,25.53 37.03,26.07 v2(37.44,26.48)
GPIO25: length 55.8
  TOP w0.135: U1.N6 v2(38.24,26.48)
  ART03 w0.102: J10.28 3.05,42.71 3.05,35.79 3.53,35.31 7.92,35.31 13.89,29.34 16.74,29.34 18.29,27.79 19.76,27.79 21.37,26.17 21.37,25.39 24.16,22.61 27.3,22.61 29.64,20.27 35.26,20.27 37.11,22.12 37.11,24.28 38.24,25.41 v2(38.24,26.48)
GPIO26: length 55.5
  TOP w0.135: J10.31 5.51,47.72 5.51,45.9 6.3,45.11 7.87,45.11 12.75,40.23 12.75,35.48 12.06,34.8 12.06,30.33 15.65,26.75 16.79,26.75 17.88,25.65 17.88,24 18.8,23.09 24.31,23.09 24.41,22.99 25.7,22.99 25.93,23.22 30.15,23.22 32.13,21.23 33.86,21.23 35,22.38 35,22.63 36.64,24.27 36.64,24.88 U1.R4
GPIO27: length 59.1
  TOP w0.135: J10.32 3.05,47.79 3.05,43.64 4.01,42.67 8.89,42.67 12.24,39.32 12.24,35.71 11.58,35.05 11.58,27.89 15.11,24.36 16.89,24.36 18.64,22.61 24.13,22.61 24.21,22.53 25.88,22.53 26.09,22.73 29.97,22.73 31.93,20.78 34.04,20.78 35.48,22.23 35.48,22.61 37.04,24.16 U1.T4
GPIO28: length 53.6
  TOP w0.135: v2(35.85,26.49) U1.N3
  ART03 w0.102: J10.33 9.1,49.31 9.1,37.35 11.88,34.57 13.67,34.57 15.42,32.82 18.69,32.82 21.67,29.84 21.67,28.32 24.41,25.58 26.7,25.58 30.3,21.97 34.6,21.97 35.46,22.83 35.46,26.16 35.79,26.49 v2(35.85,26.49)
GPIO29: length 55.8
  TOP w0.135: U1.P3 v2(35.84,25.68)
  ART03 w0.102: J10.34 5.51,50.37 7.19,50.37 8.67,48.88 8.67,37.19 12.56,33.3 13.61,33.3 14.53,32.38 18.51,32.38 21.26,29.63 21.26,28.07 24.18,25.15 26.54,25.15 30.15,21.54 34.75,21.54 35.84,22.63 v2(35.84,25.68)
GPIO30: length 52.4
  TOP w0.135: v1(34.8,23.62) 35.18,23.62 35.81,24.26 35.81,24.66 36.24,25.09 U1.R3
  ART03 w0.102: v1(34.8,23.62) 34.01,24.41 31.85,24.41 30.2,26.06 29.16,26.06 27.64,27.58 26.09,27.58 25.45,28.22 23.85,28.22 23.16,28.91 23.16,30.23 17.96,35.43 14.81,35.43 14.4,35.84 12.49,35.84 10.57,37.76 10.57,52.43 8.87,54.12 J10.35
GPIO31: length 54.6
  TOP w0.135: U1.T3 36.24,24.3 v1(34.44,22.5)
  ART03 w0.102: J10.36 5.84,52.58 7.85,52.58 9.55,50.88 9.55,37.52 12.09,34.98 13.84,34.98 15.6,33.22 18.97,33.22 22.28,29.92 22.28,28.5 23.55,27.23 25.17,27.23 25.77,26.63 26.23,26.63 30.35,22.5 v1(34.44,22.5)
GPIO32: length 72.5
  TOP w0.135: U1.P6 38.24,25.68 38.24,23.58 36.86,22.2 36.86,21.69 34.52,19.35 31.37,19.35 29.41,21.31 26.57,21.31 25.91,20.65 17.48,20.65 16.79,21.34 11.81,21.34 9.96,23.19 9.96,36.09 10.59,36.73 10.59,38.1 v1(10.06,38.63)
  ART03 w0.102: J10.37 5.69,55.52 5.69,53.59 6.22,53.06 8.2,53.06 10.06,51.21 v1(10.06,38.63)
GPIO33: length 59.5
  TOP w0.137: U1.P2 35.17,26.08 34.77,25.68 33.63,25.68 v1(32.84,24.89)
  ART03 w0.102: v1(32.84,24.89) 30.66,27.08 29.31,27.08 27.99,28.4 26.48,28.4 21.18,33.7 21.18,35.53 20.35,36.37 19.3,36.37 17.65,38.02 13.5,38.02 11.4,40.12 11.4,54.38 8,57.78 8,59.72 7.34,60.38 6.17,60.38 5.56,59.77 5.56,57.93 J10.38
GPIO34: length 53.6
  TOP w0.137: v1(32.08,24.87) 33.29,26.08 U1.P1
  ART03 w0.102: v1(32.08,24.87) 30.4,26.54 29.27,26.54 27.82,27.99 26.31,27.99 20.78,33.53 20.78,33.86 20.78,33.86 20.78,35.23 20.17,35.84 14.98,35.84 14.57,36.25 12.66,36.25 11,37.9 11,53.95 6.84,58.11 J10.39
GPIO35: length 57.4
  TOP w0.137: U1.R1 33.97,25.28 v1(33.58,24.89)
  ART03 w0.102: v1(33.58,24.89) 30.84,27.64 29.37,27.64 29.34,27.66 29.33,27.66 28.14,28.85 28.14,28.85 27.56,28.85 27.38,29.03 27.38,29.41 26.84,29.95 25.5,29.95 21.59,33.86 21.59,35.86 20.6,36.86 19.41,36.86 17.6,38.66 13.44,38.66 11.84,40.26 11.84,54.53 8.66,57.71 8.66,60.17 7.87,60.96 6.05,60.96 J10.40
HBUS_CKN: length 19.3
  TOP w0.107: U13.B1 45.63,14.07 46.42,14.07 46.58,14.22 46.58,14.45 46.68,14.55 46.83,14.55 46.93,14.45 46.93,14.17 47.03,14.07 47.18,14.07 47.39,14.27 47.79,14.27 R243.1 48.37,14.17 48.53,14.17 v1(48.89,14.53) ; U1.R14 v2(45.44,24.88)
  ART03 w0.089: v2(45.44,24.88) 45.78,24.88 45.87,24.79 45.87,24.71 46.1,24.48 46.1,24.36 46.01,24.27 45.86,24.27 45.64,24.49 45.52,24.49 45.44,24.41 45.44,23.62 46.56,22.5 46.56,19.33 48.29,17.6 48.29,15.52 48.41,15.39 48.65,15.39 48.74,15.3 48.74,15.11 48.64,15.01 48.39,15.01 48.29,14.91 48.29,14.68 48.6,14.37 48.72,14.37 v1(48.89,14.53)
HBUS_CKP: length 19.4
  TOP w0.107: U1.P14 v2(45.44,25.68) ; U13.B2 44.96,13.74 47.32,13.74 47.52,13.94 47.71,13.94 R243.2 48.25,13.84 48.58,13.84 v1(48.89,13.53)
  ART03 w0.089: v2(45.44,25.68) 45.06,25.3 45.06,23.46 46.18,22.35 46.18,19.17 47.9,17.44 47.9,14.52 v1(48.89,13.53)
HBUS_CLK_50M: length 37.7
  TOP w0.137: U1.M15 46.24,27.28 47.7,27.28 47.85,27.13 50.75,27.13 52.07,28.45 56.11,28.45 58.57,25.98 59.49,25.98 60.38,25.1 60.38,24.18 v1(60.93,23.62)
  BOTTOM w0.135: v1(60.93,23.62) 61.98,23.62 63.88,25.53 65.3,25.53 65.74,25.1 67.39,25.1 67.46,25.17 74.32,25.17 74.6,25.45 77.22,25.45 78.02,24.65 R157.2
HBUS_CS1N: length 13.9
  TOP w0.135: v2(43.84,26.48) U1.N12
  ART03 w0.102: v2(43.84,26.48) 44.22,26.1 44.22,22.56 44.5,22.28 44.5,15.02 v1(44.09,14.61)
  BOTTOM w0.135: v1(44.09,14.61) 44.77,13.94 R258.2
HBUS_CS2N: length 17.2
  TOP w0.135: v1(39.14,16.74) 40.21,15.67 41.71,15.67 41.96,15.42 41.96,14.91 42.14,14.73 42.75,14.73 43.05,14.43 43.05,13.65 U13.A3 ; U1.P9 41.04,26.04 v2(41.4,25.68)
  ART03 w0.102: v2(41.4,25.68) 41.4,25.65 41,25.25 41,23.95 41.12,23.83 41.12,21.72 39.14,19.74 v1(39.14,16.74)
HBUS_DQ0: length 3.6
  TOP w0.135: U1.T12 43.44,21.36 R249.1
HBUS_DQ1: length 4.9
  TOP w0.135: U1.T13 44.24,24.14 45.87,22.5 45.87,22.12 46,22 46.3,22 46.43,21.87 46.43,21.64 46.33,21.54 46.16,21.54 46.02,21.4 46.02,21.16 R250.1
HBUS_DQ2: length 3.8
  TOP w0.135: U1.T11 42.64,22.6 41.76,21.72 R251.1
HBUS_DQ3: length 5.1
  TOP w0.135: U1.R10 42.24,24.88 42.24,23.55 41.29,22.59 41.29,21.91 40.74,21.36 R252.1
HBUS_DQ4: length 4.3
  TOP w0.135: R253.1 39.73,21.31 40.59,22.17 40.59,22.68 41.84,23.93 U1.T10
HBUS_DQ5: length 4.6
  TOP w0.135: R254.1 42.77,22.17 43.04,22.44 43.04,24.88 U1.R11
HBUS_DQ6: length 8.4
  TOP w0.135: U1.R12 43.84,24.88 43.84,23.65 43.98,23.52 44.32,23.52 44.58,23.27 44.58,23.11 44.48,23.01 44.02,23.01 43.9,22.89 43.9,22.72 44.02,22.61 44.78,22.61 44.91,22.48 44.91,22.31 44.77,22.17 44.56,22.17 44.42,22.04 44.42,21.63 44.52,21.54 44.7,21.54 44.93,21.77 45.42,21.77 45.52,21.66 45.52,21.47 45.42,21.36 45.21,21.36 R255.1
HBUS_DQ7: length 5.4
  TOP w0.135: R256.1 46.89,22.02 44.64,24.27 44.64,24.88 U1.R13
HBUS_INTN: length 15.4
  TOP w0.135: v2(43.04,25.68) U1.P11
  ART03 w0.102: v2(43.04,25.68) 43.04,17.28 41.58,15.82 v1(39.19,15.82)
  BOTTOM w0.135: R260.2 R262.1 40.01,15.3 39.33,15.3 39.19,15.44 v1(39.19,15.82)
HBUS_RSTN: length 20.6
  TOP w0.135: v1(41.06,14.67) 41.06,14.67 40.41,14.02 40.41,13.51 41.26,12.66 42.03,12.66 U13.A4 ; U1.N9 41.04,26.85 v2(41.4,26.49)
  ART03 w0.102: v1(41.06,14.67) 41.06,14.67 40.44,15.29 39.07,15.29 38.71,15.65 38.71,16.05 38.94,16.28 39.45,16.28 39.8,16.64 39.8,19.63 41.81,21.64 41.81,26.07 41.4,26.48 v2(41.4,26.49)
  BOTTOM w0.135: R245.1 41.05,14.68 v1(41.06,14.67)
HBUS_RSTON: length 16.4
  TOP w0.135: U1.T15 47.93,22.39 47.93,21.97 48.36,21.54 48.82,21.54 49.07,21.29 49.07,19.33 v1(48.74,19)
  BOTTOM w0.135: v1(48.74,19) 47.98,18.24 47.98,14.12 48.08,14.02 48.08,12.95 47.89,12.76 R261.1 46.97,12.36 46.1,12.36 R259.2
HBUS_RWDS: length 4.6
  TOP w0.135: U1.T14 47.4,22.12 47.4,21.53 R257.1
IOREF: length 3.2
  BOTTOM w0.508: J4.2 62.37,21.42 R280.2
M10_CLK50M: length 44.3
  TOP w0.135: v1(36.86,46.58) 36.72,46.72 R160.2 ; U3.H5 v2(49.35,66.28)
  ART03 w0.102: v2(49.35,66.28) 49.1,66.28 48.72,65.89 47.5,65.89 47.17,66.22 47.17,69.8 46.46,70.51 43.23,70.51 42.77,70.05 41.55,70.05 39.5,68 39.5,65.71 40.06,65.15 40.06,62.64 41.4,61.29 41.4,59.46 41.99,58.88 42.7,58.88 43.21,58.37 43.21,50.42 40.26,47.47 37.74,47.47 v1(36.86,46.58)
M10_CLK50M_R: length 3
  TOP w0.135: v1(35.61,46.53) 35.83,46.75 R160.1
  BOTTOM w0.135: U20.4 35.66,46.58 v1(35.61,46.53)
M10_CONF_DONE: length 1.6
  TOP w0.147: U3.C5 v2(48.56,61.49)
  BOTTOM w0.135: v2(48.56,61.49) 48.56,60.85 R43.2
M10_CONFIG_SEL: length 5.5
  TOP w0.135: U3.D7 v2(46.95,62.27)
  BOTTOM w0.135: R50.1 R40.2 47.05,58.7 47.12,58.7 47.5,59.08 47.5,60.43 47.35,60.58 47.35,61.87 v2(46.95,62.27)
M10_DEV_CLRN: length 3.3
  TOP w0.305: U3.B9 v2(45.35,60.67)
  BOTTOM w0.135: v2(45.35,60.67) 44.55,59.88 44.55,59.03 44.3,58.78 R38.2
M10_DEV_OE: length 1.4
  TOP w0.135: U3.D8 v2(46.15,62.27)
  BOTTOM w0.135: R39.2 46.1,62.23 v2(46.15,62.27)
M10_JTAGEN: length 3.4
  TOP w0.135: U3.E5 v2(49.35,63.07)
  BOTTOM w0.135: R33.2 49.74,60.94 49.74,62.68 v2(49.35,63.07)
M10_NCONFIG: length 1.3
  TOP w0.135: U3.E7 v2(46.95,63.07)
  BOTTOM w0.135: R41.2 46.98,63.04 v2(46.95,63.07)
M10_NSTATUS: length 1.5
  TOP w0.135: U3.C4 v2(49.35,61.47)
  BOTTOM w0.135: v2(49.35,61.47) 49.35,60.71 R42.2
M10_TCK: length 72.2
  TOP w0.135: U3.G2 51.75,65.48 52.25,65.48 v2(52.73,65.96)
  ART03 w0.102: v2(52.73,65.96) 53.01,66.24 56.36,66.24 59.23,63.37 64.85,63.37 v1(65.58,62.64) 66.55,63.6 67.06,63.6 67.56,64.11 67.56,65.86 66.52,66.9 66.52,70.94 65.76,71.7 65.76,72.21 58.88,79.1 55.22,79.1 53.72,80.59 51.08,80.59 49.96,81.71 v1(37.82,81.71)
  BOTTOM w0.135: J1.1 38.06,83.1 38,83.03 R44.2 R45.1 v1(37.82,81.71) ; v1(65.58,62.64) 65.58,61.42 64.97,60.81 62.03,60.81 61.8,61.04 61.8,61.7 61.32,62.18 60.95,62.18 R35.2
M10_TDI: length 58.2
  TOP w0.135: U3.F5 v2(49.35,63.87)
  ART03 w0.102: v2(49.35,63.87) 49.35,64.69 49.58,64.92 56.52,64.92 58.95,62.48 v1(64.08,62.48) 65.02,61.54 66.01,61.54 66.98,62.51 68.02,62.51 68.99,63.47 68.99,66.07 68.2,66.85 68.2,70.48 66.64,72.05 66.64,72.61 58.7,80.54 56.08,80.54 54.03,82.6 v1(53.85,82.6)
  BOTTOM w0.135: J1.9 50.44,81.79 50.95,81.28 R47.2 54.5,81.95 v1(53.85,82.6) ; R36.2 v1(64.08,62.48)
M10_TDO: length 61.9
  TOP w0.135: U3.F6 v2(48.55,63.87)
  ART03 w0.102: v2(48.55,63.87) 48.93,64.26 48.93,65.61 49.2,65.89 51.54,65.89 52.3,66.65 56.54,66.65 59.41,63.78 63.83,63.78 v1(64.34,64.29) 64.62,64.01 66.85,64.01 67.11,64.26 67.11,65.51 66.07,66.55 66.07,70.79 65.41,71.45 64.9,71.45 64.67,71.68 64.67,72.36 58.5,78.54 55.17,78.54 53.67,80.04 50.72,80.04 49.45,81.31 43.41,81.31 v1(42.8,80.7)
  BOTTOM w0.135: R37.2 64.11,63.5 64.34,63.73 v1(64.34,64.29) ; v1(42.8,80.7) 42.82,80.72 J1.3
M10_TMS: length 61.1
  TOP w0.135: U3.G1 52.5,65.07 v2(52.73,65.3)
  ART03 w0.102: v2(52.73,65.3) 53.14,65.71 56.31,65.71 59.05,62.97 64.26,62.97 65.2,62.03 65.86,62.03 66.95,63.12 v1(67.56,63.12) 67.97,63.53 67.97,66.19 67.01,67.16 67.01,71.04 66.18,71.87 66.18,72.43 58.5,80.11 55.73,80.11 55.5,79.88 55.09,79.88 v1(54.56,80.42)
  BOTTOM w0.135: v1(67.56,63.12) 65.2,63.12 64.92,62.84 64.92,62.05 64.16,61.29 R34.2 ; v1(54.56,80.42) 54.55,80.4 R46.2 54.18,79.63 53.59,80.21 46.15,80.21 45.36,81 J1.5
M10_USB_CLK: length 24.7
  TOP w0.135: U3.G5 v2(49.35,65.48)
  BOTTOM w0.135: v2(49.35,65.48) 49.74,65.87 49.74,68.03 49.98,68.27 50.31,68.27 50.55,68.51 50.55,69.77 51.59,70.82 54.56,70.82 57.25,73.51 58.29,73.51 59.99,75.21 65.47,75.21 R247.1
M10_VCCA_3.3V: length 53.7
  TOP w0.305: U3.K9 v2(45.35,67.88) ; U33.8 v1(57.7,51.05) ; U3.K4 v2(50.15,67.88) ; U32.8 v1(57.72,44.54) ; U34.8 v1(57.65,57.45) ; U8.2 v1(53.83,39.7) ; U3.D4 v2(50.15,63.08) ; U11.2 v1(53.83,46.33) ; U7.2 v1(60.72,37.5)
  TOP w0.381: v2(45.34,63.12) 45.34,63.07 U3.D10
  ART03 w0.508: v1(57.72,44.54) 57.72,51.03 v1(57.7,51.05) 55.8,51.05 53.83,49.08 v1(53.83,46.33) v1(53.83,39.7) 53.83,39.03 55.37,37.5 v1(60.72,37.5)
  BOTTOM w0.305: v1(60.72,37.5) 60.49,37.73 C19.2 ; C179.2 43.43,62.61 43.73,62.92 45.14,62.92 v2(45.34,63.12) ; v1(53.83,39.7) 54.06,39.46 C23.2 ; v2(50.15,67.88) 50.65,67.88 50.78,68 C178.2 51.59,65.38 50.15,63.94 v2(50.15,63.08) 50.27,63.08 C181.2 ; v1(57.65,57.45) 57.65,58.42 C188.1 ; C168.1 57.72,45.44 v1(57.72,44.54) ; v1(53.83,46.33) 54.04,46.12 C26.2 ; C173.1 57.7,51.84 v1(57.7,51.05) ; v2(45.35,67.88) 44.63,68.59 C180.2
  vias: v1(63.58,58.52) v1(63.58,57.76)
M10_VCCIO1A: length 5.8
  TOP w0.305: v2(51.74,63.88) U3.F2
  BOTTOM w0.305: v2(51.74,63.88) 52.55,63.88 52.95,64.28 C156.1 53.21,64.9 53.21,65.63 C176.1
  BOTTOM w0.406: L2.2 55.32,66.07 C176.1
MAX_SDA: length 3
  TOP w0.135: U3.K6 v2(48.55,67.88)
  BOTTOM w0.135: R26.1 49.2,69.96 49.2,69.34 48.95,69.09 48.95,68.5 48.55,68.1 v2(48.55,67.88)
MX1+: length 7.7
  TOP w0.107: U28.13 17.96,82.58 17.48,82.1 13.74,82.1 12.61,80.98 J16.1
MX1-: length 7.7
  TOP w0.107: U28.14 17.98,81.31 17.52,81.77 13.87,81.77 13.06,80.95 13.06,80.67 J16.2
MX2+: length 14.4
  TOP w0.107: J16.3 9.78,78.44 8.99,77.65 8.99,77.01 9.4,76.61 10.05,76.61 10.81,77.37 11.93,77.37 13.2,78.64 14.99,78.64 15.33,78.3 17.51,78.3 17.98,78.77 U28.16
MX2-: length 14.3
  TOP w0.107: J16.6 11.2,74.63 10.31,75.51 10.31,76.4 10.95,77.04 12.07,77.04 13.34,78.31 14.85,78.31 15.19,77.97 17.51,77.97 17.98,77.5 U28.17
MX3+: length 8.2
  TOP w0.107: J16.4 12.85,76.58 12.8,76.44 12.82,76.41 13.26,75.97 14.66,75.97 16.14,74.49 17.51,74.49 17.98,74.96 U28.19
MX3-: length 8.3
  TOP w0.107: U28.20 17.98,73.69 17.51,74.16 16,74.16 14.52,75.64 13.12,75.64 12.55,76.21 12.51,76.29 12.37,76.34 J16.5
MX4+: length 9.6
  TOP w0.107: J16.7 12.36,72.92 12.5,72.97 12.57,73.11 13.16,73.56 14.71,73.56 16.08,72.19 16.08,70.82 16.22,70.68 17.51,70.68 17.98,71.15 U28.22
MX4-: length 9.6
  TOP w0.107: J16.8 12.84,72.68 12.79,72.82 12.83,72.89 13.27,73.23 14.57,73.23 15.75,72.05 15.75,70.68 16.08,70.35 17.51,70.35 17.98,69.88 U28.23
PMOD_D0: length 48.8
  TOP w0.135: 62.57,24.73 62.23,25.07 62.23,26.24 62.59,26.59
  TOP w0.137: 62.59,26.59 62.59,27.89 58.8,31.67 53.04,31.67 51.51,33.2 49.02,33.2 48.14,34.08 U1.D16 ; v1(78.23,14.07) 77.75,14.55 77.27,14.55 76.96,14.25 76.96,13.69 76.63,13.36 67.94,13.36 67.11,14.2 67.11,20.95 65.2,22.86 63.42,22.86 62.84,23.44 62.84,24.46 62.57,24.73
  BOTTOM w0.135: v1(78.23,14.07) 78.54,14.38
  BOTTOM w0.137: 78.54,14.38 R116.1
PMOD_D1: length 48.8
  TOP w0.135: v2(44.64,32.88) U1.F13 ; v1(62.81,30.45) 62.81,29.29 63.86,28.24 64.87,28.24 66.85,26.26 70.74,26.26 71.15,25.86 71.15,22.96 72.69,21.41 72.69,16.79 74.45,15.04 78.03,15.04 v1(78.99,14.07)
  ART03 w0.102: v1(62.81,30.45) 61.34,31.93 49,31.93 48.44,32.49 45.03,32.49 v2(44.64,32.88)
  BOTTOM w0.135: 79.55,14.66 78.99,14.1 v1(78.99,14.07)
  BOTTOM w0.137: 79.55,14.66 R118.1
PMOD_D2: length 46.9
  TOP w0.135: 67.87,14.17 68.2,13.84 73.2,13.84 73.38,14.02 v1(76.48,14.02)
  TOP w0.137: U1.D15 46.24,34.48 47.21,34.48 47.27,34.54 48.54,34.54 49.43,33.66 51.69,33.66 53.21,32.13 59.13,32.13 63.09,28.17 63.09,26.39 62.69,25.98 62.69,25.25 63.37,24.56 63.37,23.75 63.79,23.33 65.39,23.33 67.56,21.16 67.56,14.48 67.87,14.17
  BOTTOM w0.135: R120.1 v1(76.48,14.02)
PMOD_D3: length 53.4
  TOP w0.135: v1(77.5,14.07) 77.5,12.75 76.99,12.24 76.99,11.15 76.23,10.39 73.84,10.39 72.03,8.59 68.28,8.59 67.16,9.7 67.16,12.17 66.17,13.16 62.53,13.16 61.75,13.94 61.75,22.4 61.42,22.73 61.42,23.85 60.83,24.43 60.83,26.01 57.45,29.39 52.04,29.39 50.85,30.58 48.72,30.58 47.75,31.55 47.75,31.98 47.25,32.48 U1.F16
  BOTTOM w0.137: v1(77.5,14.07) R122.1
PMOD_D4: length 45.1
  TOP w0.137: U1.C16 47.02,34.88 47.8,35.66 50.95,35.66 53.57,33.05 61.95,33.05 64.01,30.99 67.94,30.99 68.35,31.39 68.35,31.78 68.58,32 69.62,32 71.63,30 71.63,23.29 73.34,21.58 73.34,17.01 v1(74.66,15.68)
  BOTTOM w0.135: R117.2 v1(74.66,15.68)
PMOD_D5: length 46.1
  TOP w0.135: v1(74.22,11.91) 73.2,10.9 68.53,10.9 67.61,11.81 67.61,12.98 66.98,13.61 62.79,13.61 62.2,14.2 62.2,22.58 61.87,22.91 61.87,24.03 61.32,24.59 61.32,26.16 57.63,29.84 52.22,29.84 51.03,31.04 49.23,31.04 47.38,32.88 46.24,32.88 U1.F15
  BOTTOM w0.135: R119.2 74.23,11.9 v1(74.22,11.91)
PMOD_D6: length 61.2
  TOP w0.135: 66.62,34.92 65.2,33.5 62.92,33.5
  TOP w0.137: v1(77.17,35.69) 76.23,34.75 75.06,34.75 73.71,36.09 71.3,36.09 70.13,34.92 66.62,34.92 ; U1.C15 46.24,35.28 46.89,35.28 47.75,36.14 51.13,36.14 53.77,33.5 62.92,33.5
  ART03 w0.102: v1(78.46,12.45) 79.5,13.49 79.5,14.71 78.69,15.52 78.69,18.44 79.53,19.28 79.53,23.01 76.94,25.6 76.94,35.46 v1(77.17,35.69)
  BOTTOM w0.135: v1(78.46,12.45) 78.55,12.53 R121.2
PMOD_D7: length 77.8
  TOP w0.135: v1(76.38,35.71) 75.92,35.26 75.29,35.26 73.81,36.73 71.17,36.73 69.82,35.38 66.67,35.38 66.22,35.84 63.88,35.84 62,33.96 53.98,33.96 51.28,36.65 47.61,36.65 U1.B16
  ART03 w0.102: v1(66.55,19.33) 65.96,19.91 65.96,22.73 67.03,23.8 67.59,23.8 68.3,24.51 73.46,24.51 76.38,27.43 v1(76.38,35.71)
  BOTTOM w0.135: v1(66.55,19.33) 66.55,14.94 65.91,14.3 65.91,10.85 68.4,8.36 72.85,8.36 74.04,7.16 R123.2
PMOD_IO0: length 17.4
  BOTTOM w0.135: J8.1 68.96,21.29 69.6,21.92 72.21,21.92 74.48,19.65 77.89,19.65 78.19,19.35 U15.1 77.25,18.93 77.06,18.75 77.06,16.76 77.57,16.26 77.97,16.26 R116.2
PMOD_IO1: length 24
  BOTTOM w0.135: 68.96,17.4 67.82,18.54 67.82,20.95 69.24,22.38 72.52,22.38 74.8,20.09 78.71,20.09 79.4,19.41 79.4,18.82 79.93,18.29 79.93,17.5 79.47,17.03 U15.3 78.19,16.66 78.44,16.41 79.35,16.41 79.55,16.21 R118.2
PMOD_IO2: length 19.3
  BOTTOM w0.135: R270.1 75.97,13.68 75.97,15.18 R120.2 76.11,15.68 76,15.8 76,16.05 75.59,16.46 U15.4 73.59,17.03 73.1,17.53 73.1,19.74 71.93,20.9 70.89,20.9 70.51,20.52 70.51,16.41 J8.3
PMOD_IO3: length 25
  BOTTOM w0.135: 74.54,18.93 72.06,21.41 70.43,21.41 69.98,20.95 69.98,16.89 69.11,16.03 68.22,16.03 67.67,15.47 67.67,13.61 J8.4 ; 76.47,18.93 76.61,18.8 76.61,16.57 R122.2 76.99,15.18 76.99,13.7 R269.1
  BOTTOM w0.137: 76.47,18.93 U15.6 74.54,18.93
PMOD_IO4: length 15
  BOTTOM w0.135: J8.7 72.49,18.95 72.49,16.99 74.69,14.8 R117.1 75.44,13.49 76,12.93 76,11.4 76.2,11.2 76.73,11.2 76.86,11.07 76.86,9.07 76.57,8.78 U16.1
PMOD_IO5: length 9.1
  BOTTOM w0.135: 71.5,17.4 71.5,16.81 74.45,13.87 74.45,13.42 R119.1 75.54,12.33 75.54,11.56 75.08,11.1 75.08,10.97 75.37,10.68 U16.3
PMOD_IO6: length 16.8
  BOTTOM w0.135: J8.9 73.61,12.75 73.61,9.37 74.79,8.2 76.68,8.2 77.4,8.92 77.4,10.48 77.59,10.68 U16.4 78.85,10.68 79.3,11.13 79.3,11.77 R265.1 79.44,11.91 R121.1
PMOD_IO7: length 12.3
  BOTTOM w0.135: U16.6 77.97,8.78 77.58,8.39 R266.1 R123.1 76.44,7.56 76.31,7.7 74.63,7.7 73.1,9.22 73.1,12.09 72.87,12.32 J8.10
PWR_GD_LED: length 54.3
  TOP w0.135: U3.H9 v2(45.35,66.28) ; Q5.1 73.14,59.42 v1(72.85,59.72)
  ART03 w0.102: v1(72.85,59.72) 71.58,60.99 71.58,66.98 v1(72.47,67.87)
  BOTTOM w0.135: v2(45.35,66.28) 45.35,66.5 45.75,66.9 45.75,67.26 45.96,67.47 46.39,67.47 47.02,68.1 47.02,71.3 48.95,73.23 53.54,73.23 57.81,77.5 67.18,77.5 68.91,75.77 68.91,74.9 72.47,71.35 v1(72.47,67.87)
RDN2: length 6.7
  TOP w0.135: v2(43.04,26.48) U1.N11
  ART03 w0.102: v2(43.04,26.48) 43.12,26.48 43.43,26.16 43.43,22.2 v1(43.92,21.72)
  BOTTOM w0.135: v1(43.92,21.72) 44.25,21.39 R13.2
REG_PG_LED_R: length 1.2
  TOP w0.135: D4.1 R235.2
RG_RXCLK: length 2.6
  TOP w0.142: R102.2 28.26,45.67 27.94,45.67 27.61,46 U14.6
RG_RXCTL: length 3.2
  TOP w0.135: 23.47,45.82 23.88,46.23 23.88,47.57 24.12,47.82 U14.48
  TOP w0.142: 23.47,45.82 R103.2
RG_RXD0: length 2.2
  TOP w0.142: R104.2 27.11,45.81 U14.5
